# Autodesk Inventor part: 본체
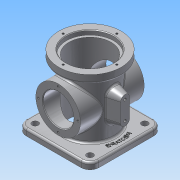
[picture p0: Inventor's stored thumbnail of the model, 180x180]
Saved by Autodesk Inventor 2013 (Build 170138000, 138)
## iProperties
Created: 2021-03
Part Number: 본체
Material: 알루미늄 6061
Document SubType Name: Modeling
Designer: Administrator
Density: 2.71 g/cm^3
Mass: 833.811 g
Surface Area: 863.886 cm^2
Volume: 307.679 cm^3
Author: Administrator
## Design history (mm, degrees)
sketch "스케치1"
  geometry: C1 r 49 at (0, 0); 1 further point
  constraints: 1 centre point, 1 coincident
  dimensions: "d0" = 98 diameter of C1
extrude "돌출1" new body sketch "스케치1" distance "d3" = 13; taper "d4" = 0 deg
sketch "스케치2"
  geometry: C1 r 38 at (0, 0); 1 further point
  constraints: 1 centre point, 1 coincident
  dimensions: "d5" = 76 diameter of C1
extrude "돌출2" join sketch "스케치2" distance "d7" = 88; taper "d8" = 0 deg
sketch "스케치3"
  geometry: L1 (-57, -57)-(57, -57); L2 (57, -57)-(57, 57); L3 (57, 57)-(-57, 57); L4 (-57, 57)-(-57, -57); L5 (-57, -57)-(57, 57); L6 (57, -57)-(-57, 57); 1 further point
  constraints: 12 end point, 2 midpoint, 2 parallel, 1 horizontal, 1 perpendicular
  dimensions: "d9" = 114 distance of L2.end L3.end; "d11" = 114 distance of L1.end L2.end
extrude "돌출3" join sketch "스케치3" distance "d12" = 10; taper "d13" = 0 deg
sketch "스케치6"
  geometry: L1 (-57, -111)-(57, -111) reference; C1 r 35 at (0, -57); 1 further point
  constraints: 1 centre point, 1 vertical alignment
  dimensions: "d27" = 70 diameter of C1; "d29" = 54 distance from line of L1 C1.centre
extrude "돌출6" join sketch "스케치6" stored distance "d30" = 100; taper "d31" = 0 deg
sketch "스케치4"
  geometry: C1 r 37 at (0, 0); 1 further point
  constraints: 1 centre point, 1 coincident
  dimensions: "d14" = 74 diameter of C1
extrude "돌출4" cut sketch "스케치4" distance "d17" = 7; taper "d18" = 0 deg
sketch "스케치5"
  geometry: C1 r 33 at (0, 0); 1 further point
  constraints: 1 centre point, 1 coincident
  dimensions: "d19" = 66 diameter of C1
extrude "돌출5" cut sketch "스케치5" stored distance "d21" = 7; taper "d22" = 0 deg
fillet "모깎기1" dims "d23" = 14
chamfer "모따기1" distance "d24" = 1; stored, may be unused: second distance "d25" = 2, angle "d26" = 45 deg
sketch "스케치7"
  geometry: C1 r 35 at (0, 0) reference; C2 r 24 at (0, 0); 1 further point
  constraints: 1 centre point, 1 coincident
  dimensions: "d32" = 48 diameter of C2
extrude "돌출7" cut sketch "스케치7" stored distance "d34" = 100; taper "d35" = 0 deg
chamfer "모따기2" distance "d36" = 1; stored, may be unused: second distance "d37" = 2, angle "d38" = 45 deg
hole "구멍1" diameter "d41" = 10; stored, may be unused: countersink angle "d45" = 90 deg, drill point angle "d47" = 118 deg; dims "d39" = 10, "d40" = 10, "d42" = 6, "d43" = 4, "d44" = 2, "d46" = 8
hole "구멍2" diameter "d50" = 10; stored, may be unused: countersink angle "d54" = 90 deg, drill point angle "d56" = 118 deg; dims "d48" = 10, "d49" = 10, "d51" = 6, "d52" = 4, "d53" = 2, "d55" = 8
hole "구멍3" diameter "d59" = 10; stored, may be unused: countersink angle "d63" = 90 deg, drill point angle "d65" = 118 deg; dims "d57" = 10, "d58" = 10, "d60" = 6, "d61" = 4, "d62" = 2, "d64" = 8
hole "구멍4" diameter "d68" = 10; stored, may be unused: countersink angle "d72" = 90 deg, drill point angle "d74" = 118 deg; dims "d66" = 10, "d67" = 10, "d69" = 6, "d70" = 4, "d71" = 2, "d73" = 8
sketch "스케치8"
  geometry: 2 further points
  constraints: 1 vertical alignment
  dimensions: "d75" = 42 distance of point (0, 0) point (0, 42)
hole "구멍5" sketch "스케치8" at (0, 42) diameter "d76" = 3.242; stored, may be unused: countersink angle "d80" = 90 deg, drill point angle "d82" = 118 deg; dims "d77" = 6, "d78" = 4, "d79" = 2, "d81" = 8
sketch "스케치9"
  geometry: C1 r 35 at (0, 0) reference; 2 further points
  constraints: 1 vertical alignment
  dimensions: "d86" = 31 distance of C1.centre point (0, 31)
hole "구멍6" sketch "스케치9" at (0, 31) diameter "d87" = 3.242; stored, may be unused: countersink angle "d91" = 90 deg, drill point angle "d93" = 118 deg; dims "d88" = 6, "d89" = 4, "d90" = 2, "d92" = 8
fillet "모깎기2" dims "d97" = 3
fillet "모깎기3" dims "d98" = 3
node "작업 평면1"
sketch "스케치10"
  geometry: L1 (7, -70)-(7, -41); L2 (-7, -41)-(-7, -70); L3 (-7, -77)-(7, -34); L4 (7, -77)-(-7, -34); L5 (50, -92)-(50, -22) reference; A1 r 7 centre (0, -41) between (0, -34) and (-7, -41); A2 r 7 centre (0, -41) between (7, -41) and (0, -34); A3 r 7 centre (0, -70) between (0, -77) and (7, -70); A4 r 7 centre (0, -70) between (-7, -70) and (0, -77); 5 further points
  constraints: 8 end point, 8 point on circle, 4 centre point, 4 midpoint, 4 point on line, 4 tangent, 2 equal radius, 1 coincident, 1 parallel, 1 vertical, 1 vertical alignment, 14 other
  dimensions: "d100" = 14 distance of L3.end L4.end; "d102" = 43 distance of L4.start L3.end; "d103" = 7 radius of A1; "d104" = 7 radius of A2; "d132" = 20 vertical distance of point (50, -57) A4.end
extrude "돌출8" join sketch "스케치10" stored distance "d105" = 100; taper "d106" = 15 deg
fillet "모깎기4" dims "d107" = 3
hole "구멍7" diameter "d110" = 4.134; stored, may be unused: countersink angle "d114" = 90 deg, drill point angle "d116" = 118 deg; dims "d108" = 10, "d109" = 10, "d111" = 8, "d112" = 4, "d113" = 2, "d115" = 10
hole "구멍8" diameter "d119" = 4.134; stored, may be unused: countersink angle "d123" = 90 deg, drill point angle "d125" = 118 deg; dims "d117" = 10, "d118" = 10, "d120" = 8, "d121" = 4, "d122" = 2, "d124" = 10
sketch "스케치11"
  geometry: L1 (28.403, -41.15)-(0, 0); L2 (0, 0)-(50, 0); A1 r 50 centre (0, 0) between (28.403, -41.15) and (50, 0); 1 further point
  constraints: 4 end point, 2 coincident, 2 point on circle, 1 centre point, 1 horizontal alignment, 1 other
  dimensions: "d128" = 100 diameter of A1
feature "엠보싱1" sketch "스케치11" dims "d130" = 0.5, "d131" = 0
fillet "모깎기5" dims "d133" = 3
node "솔리드1"
pattern_circular "원형 패턴1" dims angle "d84" = 360 deg
pattern_circular "원형 패턴2" dims angle "d95" = 360 deg
mirror "대칭1"
other parameters: "d99" = 55
